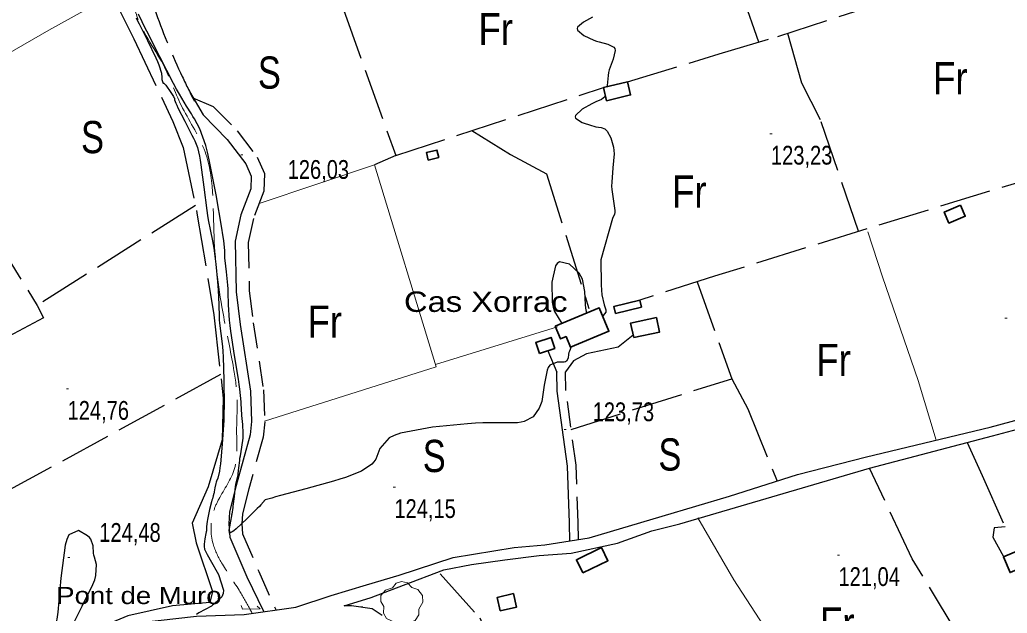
# Model space of a CAD drawing. Extents: x 483855 to 488461, y 4388206 to 4391419.
# Drawn here: x 486246.1 to 486706.5, y 4390073.1 to 4390349.6 of the extents above; entities that cross this region are included whole.
import ezdxf
from ezdxf.enums import TextEntityAlignment as Align

# ---------------------------------------------------------------- set-up
doc = ezdxf.new("R2010")
doc.units = 0
doc.header["$LTSCALE"] = 4
doc.linetypes.add('LONG_DASHED', pattern=[7.5, 6, -1.5])
doc.linetypes.add('MEDIUM_DASHED', pattern=[4.5, 3, -1.5])
for name, color, linetype, lineweight in [('15', 7, 'LONG_DASHED', 13), ('25', 7, 'LONG_DASHED', 25), ('29', 7, 'Continuous', 13), ('36', 7, 'Continuous', 25), ('38', 7, 'Continuous', 25), ('41', 7, 'Continuous', 13), ('47', 7, 'Continuous', 35), ('51', 7, 'Continuous', 13), ('7', 7, 'Continuous', 13), ('8', 7, 'Continuous', 25)]:
    doc.layers.add(name, color=color, linetype=linetype, lineweight=lineweight)
doc.layers.add('31', color=7, linetype='Continuous')
doc.layers.add('5', color=7, linetype='Continuous')

msp = doc.modelspace()

# ---------------------------------------------------------------- linework, layer by layer
at = {"layer": '15'}
msp.add_spline([(485988.87, 4391068.04), (485998.94, 4391057.53), (486002.33, 4391047.56), (486012.93, 4391033.93), (486019.04, 4391018.41), (486024.68, 4391004.24), (486026.36, 4390989.16), (486034.27, 4390970.72), (486040.06, 4390957.76), (486055.39, 4390945.7), (486063.13, 4390937.91), (486072.53, 4390923.6), (486082.62, 4390897.51), (486087.3, 4390877.34), (486091.75, 4390862.42), (486096.21, 4390844.8), (486096.99, 4390827.85), (486098.36, 4390814.05), (486099.06, 4390797.32), (486099.09, 4390782.99), (486099.7, 4390771.74), (486102.73, 4390756.37), (486111.25, 4390727.28), (486119.61, 4390707.19), (486127.67, 4390687.77), (486136.4, 4390670.46), (486146.49, 4390645.57), (486156.89, 4390619.63), (486172.84, 4390590.93), (486180.89, 4390576.54), (486187.22, 4390560.95), (486197.89, 4390546.04), (486213.23, 4390527.23), (486226.52, 4390514.2), (486236.37, 4390501.62), (486250.72, 4390486.71), (486261.18, 4390471.95), (486270.65, 4390455.91), (486275.7, 4390444), (486279.62, 4390432.82), (486283.84, 4390419.48), (486289.04, 4390402.23), (486297.99, 4390388.75), (486298.93, 4390369.09), (486300.23, 4390352.82), (486312.94, 4390328.76), (486321.38, 4390309.79), (486332.06, 4390289.33), (486336.71, 4390248.61), (486341.19, 4390211.18), (486345.81, 4390187.19), (486347.48, 4390172.64), (486347.21, 4390157.78), (486346.26, 4390140.53), (486338.86, 4390126.19), (486336.32, 4390120.03), (486336.26, 4390105.41), (486340.56, 4390096.04), (486348.38, 4390083.82), (486353.34, 4390075.2), (486354.36, 4390073.3)], degree=3, dxfattribs=at)
at = {"layer": '25'}
for p, q in [((486421.41, 4390286.4), (486518.25, 4390318.02)), ((486492.36, 4390195.42), (486496.43, 4390185.48)), ((486339.72, 4390184.31), (486190.15, 4390102.55)), ((486503.21, 4390158.78), (486578.06, 4390182.39))]:
    msp.add_line(p, q, dxfattribs=at)
for points in [[(486244.88, 4390483.25), (486259.92, 4390462.05), (486269.25, 4390445.11), (486272.48, 4390437.54), (486272.88, 4390424.19), (486278.08, 4390410.17), (486288.39, 4390391.43), (486288.71, 4390379.8), (486289.26, 4390360.9), (486299.35, 4390340.74), (486317.49, 4390302.21), (486322.31, 4390290.07), (486328.89, 4390258.65), (486336.61, 4390212.08), (486340.95, 4390173.3), (486340.46, 4390153.95), (486333.9, 4390131.96), (486326.57, 4390115.14), (486328.31, 4390105.92), (486336, 4390083.2), (486334.66, 4390078.1), (486317.33, 4390076.49), (486296.56, 4390071.88), (486282.42, 4390065.98)], [(486590.72, 4390339.21), (486578.25, 4390374.65), (486568.35, 4390409.35), (486563.81, 4390422.3), (486556.06, 4390424.65), (486557.12, 4390444.75), (486547.67, 4390444.7), (486536.01, 4390437.9)], [(486386.83, 4390382.62), (486421.41, 4390286.4), (486411.51, 4390282.11)], [(486529.45, 4390320.71), (486572.15, 4390333.69), (486599.52, 4390341.83), (486657.49, 4390360.65)], [(486637.2, 4390251.08), (486619.37, 4390302.97), (486610.74, 4390320.08), (486604.1, 4390343.32)], [(486198.02, 4390309.26), (486234.01, 4390249.12), (486254.24, 4390216.52)], [(486456.87, 4390297.98), (486474.97, 4390286.79), (486491.64, 4390277.89), (486511.39, 4390215.14)], [(486752.99, 4390276.84), (486726.92, 4390278.48), (486641.08, 4390252.28), (486570.04, 4390230.13), (486535.17, 4390218.93)], [(486327.97, 4390263.04), (486254.24, 4390216.52), (486257.18, 4390210.82), (486167.69, 4390163.12)], [(486561.84, 4390227.5), (486578.06, 4390182.39), (486585.61, 4390168.28), (486599.13, 4390134.67)], [(486532.08, 4390202.75), (486525.15, 4390197.01), (486510.3, 4390193.98), (486504.23, 4390190.67), (486500.49, 4390185.59)], [(486687.72, 4390152.59), (486694.79, 4390137.21), (486705.49, 4390113.3), (486700.31, 4390112.91), (486699.74, 4390108.57), (486704.75, 4390099.5)], [(486614.36, 4390034.12), (486650.38, 4390057.11), (486653.74, 4390050.87), (486682.69, 4390064.67), (486662.19, 4390098.45), (486642.19, 4390140.66)], [(486442.05, 4390091.4), (486460.54, 4390070.95), (486475.3, 4390037.75), (486471.59, 4390030.94)]]:
    msp.add_lwpolyline(points, dxfattribs=at)
at = {"layer": '29'}
msp.add_lwpolyline([(486421.7, 4390068.53), (486417.16, 4390070.65), (486415.75, 4390073.19), (486415.85, 4390076.17), (486414.48, 4390078.58), (486414.52, 4390081.33), (486416.68, 4390083.93), (486419.87, 4390084.93), (486421.52, 4390087.12), (486424.09, 4390087.95), (486426.95, 4390087.3), (486428.9, 4390085.03), (486431.71, 4390084.21), (486433.84, 4390081.36), (486434.08, 4390078.23), (486432.2, 4390075.08), (486432.2, 4390072.4), (486430.38, 4390069.79), (486426.76, 4390068.45), (486423.99, 4390069.08)], close=True, dxfattribs=at)
at = {"layer": '36'}
for points in [[(486640.83, 4390145.94), (486698.5, 4390159.83), (486758.93, 4390176.07), (486791.22, 4390186.64), (486839.63, 4390204.18), (486901.91, 4390227.03), (486940.89, 4390244.11), (486987.63, 4390260.3), (487028.54, 4390277.74), (487073.52, 4390294.84), (487105.72, 4390306.34), (487169.01, 4390327.72), (487231.07, 4390349.35)], [(486553.86, 4390114.84), (486642.19, 4390140.66), (486699.55, 4390155.69), (486760.15, 4390171.97), (486792.61, 4390182.6), (486841.09, 4390200.16), (486903.51, 4390223.06), (486942.45, 4390240.13), (486989.17, 4390256.31), (487030.14, 4390273.77), (487075, 4390290.83), (487107.12, 4390302.3), (487170.4, 4390323.68), (487232.26, 4390345.24)], [(486224.58, 4390051.52), (486260.52, 4390060.64), (486292.83, 4390067.76), (486328.44, 4390071.68), (486350.81, 4390072.48), (486374.78, 4390075.95), (486391.31, 4390081.39), (486407.72, 4390086.31), (486423.02, 4390090.89), (486448.18, 4390099.14), (486476.64, 4390103.74), (486490.83, 4390104.97), (486511.49, 4390108.24), (486545.64, 4390118.35), (486577, 4390127.61), (486608.74, 4390137.74), (486640.83, 4390145.94)], [(486397.31, 4390076.61), (486409.89, 4390080.4), (486425.04, 4390086.2), (486443.78, 4390093.35), (486456.75, 4390095.85), (486472.28, 4390098.05), (486488.21, 4390100.01), (486503.1, 4390101.1), (486524.85, 4390105.79), (486540.82, 4390111.52), (486553.86, 4390114.84)], [(486415.1, 4390072.08), (486410.47, 4390075.13), (486400.81, 4390076.59), (486397.31, 4390076.61)]]:
    msp.add_lwpolyline(points, dxfattribs=at)
at = {"layer": '38'}
for points in [[(486325.26, 4390316.28), (486331.6, 4390305.34), (486342.88, 4390293.88), (486351.44, 4390282.5), (486353.99, 4390276.83), (486353.78, 4390270.93), (486349.15, 4390258.7), (486346.54, 4390246.46), (486347.03, 4390222.89), (486348.93, 4390207.59), (486353.63, 4390176.61), (486354.18, 4390162.45), (486353.51, 4390156.3), (486346.95, 4390132.6), (486343.9, 4390120.43), (486343.53, 4390114.79), (486343.99, 4390108.55), (486351.97, 4390090.02), (486359.67, 4390074.14)], [(486502.61, 4390106.55), (486502.39, 4390115.2), (486501.45, 4390141.68), (486496.67, 4390176.56), (486496.43, 4390185.48)]]:
    msp.add_lwpolyline(points, dxfattribs=at)
at = {"layer": '38', "linetype": 'MEDIUM_DASHED'}
for points in [[(486326.78, 4390313.21), (486336.35, 4390309.22), (486347.51, 4390297.88), (486356.73, 4390285.63), (486360.14, 4390278.03), (486359.85, 4390269.71), (486355.03, 4390256.97), (486352.66, 4390245.88), (486353.13, 4390223.34), (486354.98, 4390208.42), (486359.72, 4390177.19), (486360.3, 4390162.24), (486359.53, 4390155.15), (486352.86, 4390131.04), (486349.96, 4390119.48), (486349.65, 4390114.81), (486350, 4390110.03), (486357.54, 4390092.54), (486365.44, 4390074.81)], [(486506.65, 4390107.49), (486506.45, 4390115.32), (486505.5, 4390142.03), (486500.72, 4390176.89), (486500.49, 4390185.59)]]:
    msp.add_lwpolyline(points, dxfattribs=at)
at = {"layer": '38', "linetype": 'LONG_DASHED'}
msp.add_spline([(486193.4, 4390565.76), (486212.3, 4390545.54), (486236.35, 4390513.02), (486254.31, 4390495.34), (486265.36, 4390479.16), (486280.33, 4390458.48), (486285.22, 4390447.54), (486290.89, 4390422.12), (486299.92, 4390402.33), (486303.42, 4390375.85), (486309.68, 4390352.53), (486321.88, 4390323.15), (486327.83, 4390311.08)], degree=3, dxfattribs=at)
at = {"layer": '41'}
msp.add_lwpolyline([(486356.79, 4390076.33), (486358.22, 4390075.14), (486349.89, 4390075.05), (486349.36, 4390076.7)], dxfattribs=at)
at = {"layer": '47'}
for points in [[(486519.71, 4390311.92), (486530.91, 4390314.61), (486529.45, 4390320.71), (486518.25, 4390318.02)], [(486436.57, 4390284.25), (486441.46, 4390285.44), (486440.61, 4390288.91), (486435.72, 4390287.72)], [(486684.73, 4390263.22), (486677.11, 4390260.05), (486679.26, 4390254.89), (486686.88, 4390258.06)], [(486495.73, 4390206.86), (486516.27, 4390215.37), (486520.77, 4390204.48), (486502.82, 4390197.07), (486500.77, 4390202.01), (486498.2, 4390200.94)], [(486523.77, 4390212.83), (486535.93, 4390215.76), (486535.17, 4390218.93), (486523.01, 4390216)], [(486532.34, 4390201.52), (486544.34, 4390204.03), (486542.91, 4390210.84), (486530.91, 4390208.33)], [(486488.4, 4390194.1), (486495.51, 4390196.48), (486493.79, 4390201.61), (486486.68, 4390199.23)], [(486508.59, 4390091.89), (486520.31, 4390097.54), (486517.35, 4390103.68), (486505.63, 4390098.03)], [(486717.73, 4390096.24), (486707.82, 4390092.07), (486704.75, 4390099.36), (486714.66, 4390103.53)], [(486470.14, 4390074.19), (486477.76, 4390075.99), (486476.28, 4390082.23), (486468.66, 4390080.43)]]:
    msp.add_lwpolyline(points, close=True, dxfattribs=at)
at = {"layer": '51'}
msp.add_line((486439.89, 4390189.05), (486496.78, 4390206.49), dxfattribs=at)
for points in [[(486156.56, 4390405.55), (486205.92, 4390313.81), (486259.73, 4390344.73), (486289.25, 4390361.18)], [(486357.71, 4390264.04), (486411.51, 4390282.11), (486440.25, 4390187.87), (486360.29, 4390162.6)], [(486673.3, 4390153.76), (486664.88, 4390181.51), (486648.37, 4390229.81), (486641.41, 4390250.85)], [(486532.69, 4389983.74), (486581.07, 4390012.11), (486614.36, 4390034.12), (486578.95, 4390088.69), (486562.24, 4390117.52)]]:
    msp.add_lwpolyline(points, dxfattribs=at)
at = {"layer": '7'}
for p, q in [((486595.81, 4390296.52), (486596.81, 4390296.52)), ((486349.12, 4390286.66), (486350.12, 4390286.66)), ((486705.36, 4390210.67), (486706.36, 4390210.67)), ((486267.91, 4390177.61), (486268.91, 4390177.61)), ((486499.88, 4390158.78), (486500.88, 4390158.78)), ((486420.26, 4390131.87), (486421.26, 4390131.87)), ((486627.29, 4390100.17), (486628.29, 4390100.17)), ((486268.49, 4390099.14), (486269.49, 4390099.14)), ((486404.98, 4390076.04), (486405.98, 4390076.04))]:
    msp.add_line(p, q, dxfattribs=at)
at = {"layer": '8'}
for points in [[(486300.33, 4390350.49), (486300.97, 4390349.21), (486301.74, 4390347.68), (486305.68, 4390339.95), (486309.61, 4390331.88), (486310.37, 4390330.13), (486311, 4390328.59), (486312.12, 4390324.78), (486312.33, 4390322.69), (486312.38, 4390322.23), (486312.43, 4390321.83), (486312.62, 4390320.84), (486312.82, 4390320.33), (486312.88, 4390320.24), (486312.95, 4390320.16), (486313.23, 4390320.03), (486313.87, 4390319.46), (486314.17, 4390319.09), (486314.51, 4390318.64), (486316.19, 4390316.27), (486317.73, 4390313.88), (486318, 4390313.42), (486318.19, 4390313.04), (486318.31, 4390312.38), (486318.82, 4390310.8), (486319.27, 4390309.83), (486319.84, 4390308.64), (486323.02, 4390302.43), (486326.4, 4390295.86), (486327.1, 4390294.44), (486327.7, 4390293.2), (486329.04, 4390290.13), (486329.89, 4390286.11), (486330.19, 4390284.26), (486330.51, 4390282.09), (486331.88, 4390271.6), (486333.31, 4390260.79), (486333.66, 4390258.43), (486334, 4390256.34), (486335.06, 4390251.07), (486336.01, 4390246.58), (486336.28, 4390244.99), (486336.55, 4390243.25)], [(486340.33, 4390252.49), (486337.66, 4390268.1), (486334.45, 4390284.41), (486333.62, 4390287.95), (486332.81, 4390291.06), (486330.07, 4390298.78), (486327.54, 4390303.42), (486326.86, 4390304.6), (486326.19, 4390305.74), (486323.84, 4390309.45), (486320.53, 4390315.04), (486319.26, 4390317.36), (486317.84, 4390320.01), (486311.4, 4390332.38), (486305.36, 4390344.29), (486304.17, 4390346.65), (486303.21, 4390348.61), (486301.48, 4390352.31)], [(486513.11, 4390350.87), (486508.98, 4390348.45), (486506.13, 4390346.18), (486506, 4390345.52), (486506.16, 4390344.85)], [(486506.16, 4390344.85), (486509.09, 4390342.35), (486513.74, 4390340.17), (486514.97, 4390339.7), (486516.17, 4390339.29), (486520.33, 4390338.33), (486523.12, 4390336.9), (486523.47, 4390336.2), (486523.64, 4390335.37), (486522.69, 4390331.27), (486520.95, 4390326.38), (486520.62, 4390325.04), (486520.35, 4390323.72), (486519.9, 4390319), (486519.84, 4390318.4)], [(486519.16, 4390314.22), (486518.94, 4390313.75), (486517.33, 4390312.44), (486514.74, 4390311.45), (486513.8, 4390311), (486512.78, 4390310.47), (486508.29, 4390307.9), (486505.19, 4390305.09), (486505.03, 4390304.4), (486505.18, 4390303.75), (486508.26, 4390301.73), (486512.7, 4390300.31), (486513.71, 4390300.04), (486514.62, 4390299.82), (486517.1, 4390299.48), (486518.94, 4390298.74), (486519.44, 4390298.27), (486519.94, 4390297.7), (486521.73, 4390294.67), (486522.95, 4390290.23), (486523.1, 4390288.76), (486523.15, 4390287.19), (486522.66, 4390280.66), (486522.06, 4390273.89), (486522.05, 4390272.17), (486522.11, 4390270.51), (486522.9, 4390265.09), (486523.57, 4390260.82), (486523.55, 4390259.89), (486523.45, 4390259.06), (486522.37, 4390257.02), (486517, 4390237.75), (486517.12, 4390226.05), (486517.26, 4390223.6), (486517.45, 4390221.49), (486518.55, 4390216.73), (486519.35, 4390214.43), (486519.35, 4390213.87), (486519.26, 4390213.36), (486518.12, 4390211.78), (486517.87, 4390211.49)], [(486491.93, 4390186.36), (486490.62, 4390179.41), (486489.43, 4390171.83), (486488.91, 4390170.14), (486488.31, 4390168.63), (486485.45, 4390164.64), (486481.24, 4390162.48), (486479.8, 4390162.12), (486478.23, 4390161.86), (486471.53, 4390161.77), (486461.92, 4390161.82), (486458.51, 4390161.65), (486454.77, 4390161.39), (486438.58, 4390159.79), (486423.66, 4390156.98), (486420.73, 4390155.96), (486418.32, 4390154.84), (486413.95, 4390149.91), (486412.06, 4390144.88), (486411.2, 4390143.69), (486410.21, 4390142.59), (486405.42, 4390139.34), (486397.97, 4390136.43), (486395.29, 4390135.55), (486392.34, 4390134.63), (486379.48, 4390131.02), (486367.69, 4390127.89), (486365.41, 4390127.28), (486363.57, 4390126.78), (486360.5, 4390125.89), (486360.27, 4390125.71), (486360.22, 4390125.67), (486360.17, 4390125.62), (486360.03, 4390125.44), (486359.93, 4390125.26), (486359.9, 4390125.21), (486359.88, 4390125.16), (486359.82, 4390124.96), (486358.57, 4390123.62), (486357.81, 4390122.85), (486356.86, 4390121.91), (486351.9, 4390117.04), (486346.93, 4390112.38), (486345.97, 4390111.57), (486345.2, 4390110.96), (486343.91, 4390110.49), (486343.82, 4390111.23), (486343.8, 4390111.38), (486343.79, 4390111.52), (486343.77, 4390111.81), (486343.87, 4390112.54), (486343.94, 4390112.94), (486344.02, 4390113.43), (486344.46, 4390115.93), (486344.92, 4390118.45), (486345.02, 4390118.95), (486345.1, 4390119.37), (486345.29, 4390120.18), (486345.49, 4390121.46), (486345.58, 4390122.17), (486345.68, 4390123.05), (486346.16, 4390127.51), (486346.71, 4390132.09), (486346.85, 4390133.03), (486346.99, 4390133.84), (486347.44, 4390135.59), (486347.82, 4390136.9), (486347.92, 4390137.43), (486348.01, 4390138.04), (486348.29, 4390140.82), (486348.65, 4390144.29), (486348.79, 4390145.32), (486348.95, 4390146.39), (486349.65, 4390150.49), (486350.21, 4390154.74), (486350.28, 4390155.9), (486350.31, 4390157.05), (486350.11, 4390161.12), (486349.71, 4390165.18), (486349.62, 4390166.32), (486349.53, 4390167.47), (486349.28, 4390171.66), (486348.69, 4390177.54), (486348.39, 4390179.75), (486348.03, 4390182.22), (486346.26, 4390193.23), (486344.52, 4390204.54), (486344.19, 4390207.19), (486343.92, 4390209.64), (486343.49, 4390216.76), (486343.32, 4390222.64), (486343.22, 4390224.3), (486343.1, 4390225.97), (486342.44, 4390232.14), (486341.84, 4390237.46), (486341.74, 4390238.59), (486341.67, 4390239.58), (486341.68, 4390241.95), (486341.2, 4390246.82), (486340.81, 4390249.39), (486340.33, 4390252.49)], [(486336.55, 4390243.25), (486337.54, 4390235.7), (486338.36, 4390227.65), (486338.51, 4390225.58), (486338.64, 4390223.6), (486338.85, 4390217.02), (486339.01, 4390211.23), (486339.11, 4390209.74), (486339.24, 4390208.29), (486339.88, 4390203.43), (486340.58, 4390197.34), (486340.74, 4390195.11), (486340.89, 4390192.65), (486341.29, 4390181.77), (486341.37, 4390169.63), (486341.3, 4390166.36), (486341.2, 4390163.14), (486340.53, 4390151.85), (486339.67, 4390142.73), (486339.44, 4390140.88), (486339.22, 4390139.31), (486338.47, 4390136.1), (486337.84, 4390134.61), (486337.69, 4390134.13), (486337.55, 4390133.62), (486337.13, 4390131.57), (486336.8, 4390129.64), (486336.71, 4390129.22), (486336.62, 4390128.84), (486336.33, 4390127.86), (486335.9, 4390126.47), (486335.73, 4390125.83), (486335.53, 4390125.08), (486334.62, 4390121.46), (486333.77, 4390117.61), (486333.6, 4390116.72), (486333.47, 4390115.9), (486333.24, 4390113.59), (486333.1, 4390111.58), (486333.03, 4390110.96), (486332.93, 4390110.31), (486332.46, 4390107.72), (486332.06, 4390105.29), (486332.02, 4390104.74), (486332.01, 4390104.24), (486332.21, 4390102.89), (486333.45, 4390100.48), (486334.09, 4390099.32), (486334.86, 4390097.94), (486338.71, 4390091.18), (486341.07, 4390083.93), (486340.9, 4390082.25), (486340.37, 4390080.71), (486335.47, 4390076.34), (486329.61, 4390073.27), (486328.47, 4390072.55)], [(486510.45, 4390212.96), (486510.29, 4390213.67), (486510.04, 4390215.31), (486509.83, 4390216.96), (486509.5, 4390223.04), (486508.4, 4390228.75), (486507.71, 4390230.17), (486506.85, 4390231.52), (486502.35, 4390235.8), (486497.68, 4390236.84), (486496.72, 4390236.13), (486495.89, 4390235), (486494.1, 4390227.33), (486494.33, 4390217.98), (486494.78, 4390215.78), (486495.4, 4390213.75), (486498.84, 4390208.15)], [(486503.13, 4390197.2), (486502.36, 4390195.2), (486502.16, 4390194.53), (486502, 4390193.89), (486501.75, 4390191.88), (486500.96, 4390190.53), (486500.46, 4390190.3), (486499.84, 4390190.14), (486496.6, 4390190.09), (486493.23, 4390188.68), (486492.53, 4390187.66), (486491.93, 4390186.36)], [(486280.54, 4390101.12), (486280.28, 4390104.5), (486279.24, 4390107.64), (486278.59, 4390108.43), (486277.77, 4390109.19), (486273.51, 4390111.65), (486269.03, 4390109.61), (486268.08, 4390107.54), (486267.25, 4390104.81), (486265.31, 4390089.48), (486263.89, 4390073.53), (486263.4, 4390070.4), (486262.86, 4390067.84), (486260.57, 4390063.26), (486258.23, 4390062.38), (486257.66, 4390062.15), (486257.14, 4390061.94), (486255.54, 4390061.22), (486251.31, 4390060.43), (486249.13, 4390060.17), (486246.51, 4390059.89), (486233.37, 4390058.73)], [(486270.58, 4390067.04), (486275.21, 4390076.37), (486280.2, 4390086.49), (486281.05, 4390088.72), (486281.66, 4390090.7), (486281.91, 4390095.78), (486280.89, 4390099.23), (486280.69, 4390100.18), (486280.54, 4390101.12)]]:
    msp.add_lwpolyline(points, dxfattribs=at)

# ---------------------------------------------------------------- texts
at = {"layer": '31'}
for s, width, p in [('Fr', 0.85, (486467.99, 4390337.8)), ('S', 0.8, (486362.49, 4390317.53)), ('Fr', 0.85, (486679.93, 4390314.95)), ('S', 0.8, (486280.04, 4390287.47)), ('Fr', 0.85, (486558.26, 4390262.09)), ('Fr', 0.85, (486388.34, 4390201.49)), ('Fr', 0.85, (486625.5, 4390183.61)), ('S', 0.8, (486439.34, 4390138.89)), ('S', 0.8, (486549.21, 4390139.59)), ('Fr', 0.85, (486627.21, 4390060.83))]:
    msp.add_text(s, height=15, dxfattribs=dict(at, width=width)).set_placement(p, align=Align.CENTER)
at = {"layer": '5', "width": 1.2}
msp.add_text('Cas Xorrac', height=9.5, dxfattribs=at).set_placement((486425.24, 4390213.51))
msp.add_text('Pont de Muro', height=8, dxfattribs=at).set_placement((486340.19, 4390077.37), align=Align.RIGHT)
at = {"layer": '7', "width": 0.8}
for s, p in [('123,23', (486596.31, 4390282.15)), ('126,03', (486371.01, 4390275.5)), ('124,76', (486268.41, 4390163.24)), ('123,73', (486513.21, 4390162.59)), ('124,15', (486420.76, 4390117.5)), ('124,48', (486283.2, 4390106.37)), ('121,04', (486627.79, 4390085.8))]:
    msp.add_text(s, height=8.75, dxfattribs=at).set_placement(p)

doc.saveas('drawing.dxf')
